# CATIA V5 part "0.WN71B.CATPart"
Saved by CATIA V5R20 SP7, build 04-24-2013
Part number: 0.WN71B
Material "Nessuno"
Bounding box of the stored display mesh (mm): x 0 to 149.213, y -135.185 to 0, z -56.919 to 41.584
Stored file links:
  C:\Users\designer2\Desktop\Ottobre 2022\25-10-2022\04\Yori Evo 48V\0.WN71B.CATPart
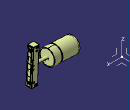
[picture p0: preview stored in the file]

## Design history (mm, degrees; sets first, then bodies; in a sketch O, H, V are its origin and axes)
AxisSystem1: origin (0, 0, 0), X (1, 0, 0), Y (0, 1, 0), Z (0, 0, 1)
Set1
  DatumSurface1
Body1 (main body), material "Nessuno"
